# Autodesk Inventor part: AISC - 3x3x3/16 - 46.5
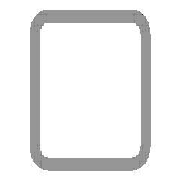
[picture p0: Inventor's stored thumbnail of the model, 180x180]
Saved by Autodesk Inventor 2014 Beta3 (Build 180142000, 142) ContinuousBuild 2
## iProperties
IsCustomPart: 1
_CCFamilyMember: 9
_CCFamilyDisplayName: ANSI AISC (Square) - Tube
_FrameMemberDoc: Frame Member File
_Version: 15.0.0
_GetPNFromCC: 1
Created: 2011-01
Part Number: AISC - 3x3x3/16 - 46.5
Material: Steel, Mild
Description: Tube
Document SubType Name: Modeling
Standard: ANSI
Designer: Beta-8540w
Standards Organization: ANSI
Language: en-US
Size Designation: 3x3x3/16
Categories: <MemberInstance><Categories><Category DisplayName="Structural Shapes" InternalName="089c4875-fa83-4c05-b084-43b9cc11f5ed" Mnemonic="GRDR"><CategoryParameter Dis
Stock Number: 3x3x3/16
Density: 7.86 g/cm^3
Appearance: Steel
G_W: 3.000 in
G_H: 3.000 in
G_L: 46.500 in
Author: Beta-8540w
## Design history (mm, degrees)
node "Start plane"
node "End plane"
sketch "Sketch"
  geometry: L1 (-38.1, -28.575)-(-38.1, 28.575); L2 (-28.575, 38.1)-(28.575, 38.1); L3 (38.1, 28.575)-(38.1, -28.575); L4 (28.575, -38.1)-(-28.575, -38.1); L5 (-28.575, 33.337)-(28.575, 33.338); L6 (33.338, 28.575)-(33.338, -28.575); L7 (28.575, -33.337)-(-28.575, -33.338); L8 (-33.338, -28.575)-(-33.338, 28.575); L9 (0, 56.102)-(0, -56.102) reference; L10 (-56.102, 0)-(56.102, 0) reference; A1 r 9.525 centre (-28.575, -28.575) between (-38.1, -28.575) and (-28.575, -38.1); A2 r 9.525 centre (-28.575, 28.575) between (-28.575, 38.1) and (-38.1, 28.575); A3 r 9.525 centre (28.575, 28.575) between (38.1, 28.575) and (28.575, 38.1); A4 r 9.525 centre (28.575, -28.575) between (28.575, -38.1) and (38.1, -28.575); A5 r 4.763 centre (-28.575, 28.575) between (-28.575, 33.337) and (-33.338, 28.575); A6 r 4.763 centre (28.575, 28.575) between (33.338, 28.575) and (28.575, 33.338); A7 r 4.763 centre (28.575, -28.575) between (28.575, -33.337) and (33.338, -28.575); A8 r 4.763 centre (-28.575, -28.575) between (-33.338, -28.575) and (-28.575, -33.338)
  constraints: 16 end point, 16 point on circle, 8 centre point, 8 tangent, 4 parallel, 3 equal radius, 2 perpendicular, 7 other
  dimensions: "d10" = 76.2 distance between parallel lines of L2 L4 (= G_H); "d11" = 76.2 distance between parallel lines of L1 L3 (= G_W); "d12" = 4.7625 distance between parallel lines of L3 L6 (= G_T); "d15" = 38.1 distance between parallel lines of L2 L10 (= 0.5 x d10); "d16" = 38.1 distance between parallel lines of L9 L3 (= 0.5 x d11); "d17" = 9.525 radius of A1 (= G_IR)
extrude "Body" new body sketch "Sketch" stored distance "d3" = 1181.1 (= G_L); taper "d4" = 0 deg
node "Driven Length"
  sketch "Sketch3"
    geometry: L1 (0, 0)-(10, 0) reference
    constraints: 2 end point, 1 horizontal
  workplane "Work Plane3"
  sketch "Sketch4"
    geometry: L1 (-2, 38.1)-(12, 38.1) reference; L2 (-2, 1219.2)-(12, 1219.2) reference
    dimensions: "d19" = 1181.1 distance between parallel lines of L1 L2 (derived)
workplane "Work Plane4"
split "Split1"
body "Solid1"
other parameters: "G_W" = 76.2 [user parameter; used in 1 equation term], "G_H" = 76.2 [user parameter; used in 1 equation term], "G_T" = 4.7625 [user parameter; used in 1 equation term], "G_IR" = 9.525 [user parameter; used in 1 equation term], "G_L" = 1181.1 (= d19) [user parameter; used in 1 equation term], "G_OFFSET_START" = -38.1 [user parameter; used in 1 equation term], "G_OFFSET_END" = 0 [user parameter; used in 1 equation term], "d13" = 38.1 (= -G_OFFSET_START), "d14" = 1219.2 (= G_OFFSET_END + B_L), "B_L" = 1219.2 [user parameter; used in 1 equation term], "d18" = 90 deg
